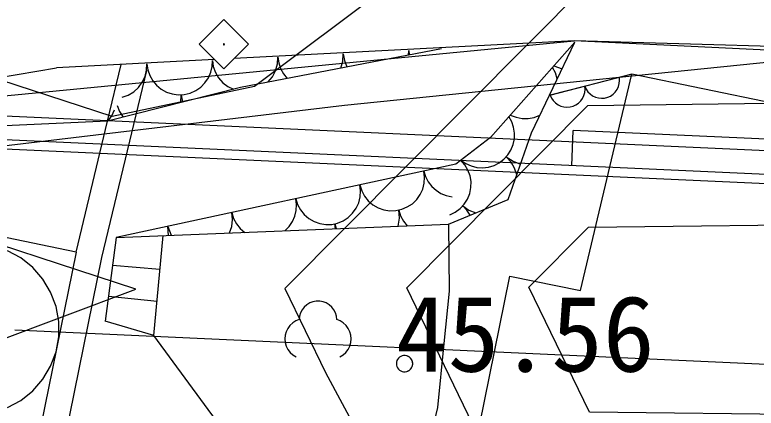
# Model space of a CAD drawing. Extents: x 42655 to 43811, y -141820 to -141156.
# Drawn here: x 43648.75 to 43660.06, y -141351.2 to -141345.21 of the extents above; entities that cross this region are included whole.
import ezdxf

# ---------------------------------------------------------------- set-up
doc = ezdxf.new("R2010")
doc.units = 0
for name, color, linetype in [('D-BMK-HTXT_1', 7, 'Continuous'), ('ZE_HICN', 7, 'Continuous'), ('ZE_LWCN', 7, 'Continuous'), ('地形', 7, 'Continuous'), ('現況道路ﾊｯﾁ', 7, 'Continuous')]:
    doc.layers.add(name, color=color, linetype=linetype)

msp = doc.modelspace()

# ---------------------------------------------------------------- linework, layer by layer
at = {"layer": 'D-BMK-HTXT_1'}
msp.add_lwpolyline([(43648.635, -141351.192), (43648.84, -141351.082), (43649.023, -141350.936), (43649.176, -141350.761), (43649.295, -141350.561), (43649.377, -141350.343), (43649.419, -141350.113), (43649.419, -141349.88), (43649.377, -141349.651), (43649.295, -141349.433), (43649.176, -141349.233), (43649.023, -141349.057), (43648.84, -141348.912), (43648.635, -141348.801)], dxfattribs=at)
at = {"layer": 'ZE_HICN'}
msp.add_lwpolyline([(43670.166, -141358.665), (43667.725, -141358.014), (43663.61, -141355.487), (43662.608, -141351.884), (43660.983, -141351.301), (43657.517, -141351.264), (43656.594, -141349.358), (43657.503, -141348.444), (43661.814, -141348.392), (43662.588, -141347.666), (43663.879, -141347.759), (43667.681, -141348.645), (43668.638, -141349.3)], dxfattribs=at)
at = {"layer": 'ZE_LWCN'}
for points in [[(43670.156, -141340.015), (43667.636, -141339.291), (43665.818, -141339.189), (43662.55, -141339.651), (43660.092, -141340.198), (43657.476, -141342.639), (43656.548, -141343.195), (43652.405, -141346.296), (43650.235, -141346.757), (43647.315, -141345.805)], [(43672.041, -141343.121), (43667.648, -141341.858), (43663.811, -141341.644), (43662.56, -141341.821), (43661.619, -141342.03), (43660.391, -141343.177), (43658.75, -141344.716), (43657.486, -141344.731), (43652.867, -141349.375), (43653.488, -141350.658), (43656.108, -141355.523), (43657.543, -141356.746), (43661.312, -141357.098), (43662.633, -141357.221), (43664.475, -141357.711), (43667.733, -141359.712), (43669.028, -141360.057)], [(43669.597, -141359.361), (43667.729, -141358.863), (43663.03, -141355.977), (43662.627, -141355.87), (43662.338, -141355.843), (43658.775, -141355.51), (43657.822, -141355.168), (43657.535, -141355.165), (43654.731, -141349.366), (43657.495, -141346.587), (43660.282, -141346.554), (43662.572, -141344.405), (43666.396, -141344.681), (43667.663, -141344.976), (43671.208, -141347.405)], [(43647.337, -141350.606), (43650.597, -141349.386), (43647.327, -141348.32), (43642.867, -141349.423), (43647.337, -141350.606)]]:
    msp.add_lwpolyline(points, dxfattribs=at)
at = {"layer": '地形'}
for p, q in [((43646.378, -141346.651), (43657.284, -141345.602)), ((43668.134, -141346.119), (43657.284, -141345.602)), ((43665.232, -141347.509), (43626.082, -141345.728)), ((43651.797, -141345.888), (43649.384, -141346.013)), ((43650.163, -141346.825), (43650.371, -141345.962)), ((43665.216, -141347.869), (43626.066, -141346.088)), ((43644.324, -141346.875), (43649.384, -141346.013)), ((43658.167, -141346.11), (43656.908, -141346.434)), ((43657.383, -141349.41), (43658.167, -141346.11)), ((43667.506, -141348.037), (43658.167, -141346.11)), ((43666.822, -141348.082), (43626.06, -141346.228)), ((43657.974, -141346.159), (43656.92, -141346.431)), ((43650.163, -141346.825), (43644.868, -141347.075)), ((43649.682, -141348.821), (43650.163, -141346.825)), ((43657.247, -141347.506), (43657.271, -141346.967)), ((43665.24, -141347.329), (43657.271, -141346.967)), ((43649.682, -141348.821), (43644.802, -141347.813)), ((43650.297, -141348.599), (43650.125, -141349.873)), ((43650.871, -141350.091), (43651.01, -141348.571)), ((43649.682, -141348.821), (43649.126, -141351.553)), ((43650.963, -141349.089), (43650.24, -141349.024)), ((43655.415, -141353.55), (43656.305, -141349.19)), ((43656.305, -141349.19), (43657.383, -141349.41)), ((43650.918, -141349.577), (43650.176, -141349.499)), ((43650.871, -141350.091), (43650.125, -141349.873)), ((43667.605, -141350.87), (43648.749, -141350.013)), ((43651.943, -141351.553), (43650.871, -141350.091))]:
    msp.add_line(p, q, dxfattribs=at)
for points in [[(43549.208, -141319.961), (43556.867, -141320.753), (43567.431, -141322.178), (43571.973, -141322.864), (43574.086, -141324.131), (43583.297, -141331.692), (43590.642, -141338.347), (43593.759, -141341.303), (43600.265, -141345.426), (43603.065, -141346.799), (43608.248, -141348.229), (43613.847, -141348.387), (43631.813, -141349.201), (43653.781, -141346.583), (43661.115, -141345.834), (43670.949, -141346.829), (43671.768, -141347.675)], [(43651.938, -141345.279), (43651.563, -141345.654), (43651.938, -141346.029), (43652.313, -141345.654), (43651.938, -141345.279)], [(43657.295, -141345.623), (43656.007, -141347.076), (43655.48, -141347.482), (43650.297, -141348.599), (43655.368, -141348.397), (43656.277, -141348.02), (43656.634, -141347.002), (43657.295, -141345.623)], [(43651.931, -141345.654), (43651.931, -141345.656), (43651.931, -141345.657), (43651.932, -141345.658), (43651.933, -141345.659), (43651.934, -141345.66), (43651.935, -141345.661), (43651.936, -141345.662), (43651.937, -141345.662), (43651.939, -141345.662), (43651.94, -141345.662), (43651.941, -141345.661), (43651.942, -141345.661), (43651.943, -141345.66), (43651.944, -141345.659), (43651.945, -141345.658), (43651.946, -141345.656), (43651.946, -141345.655), (43651.946, -141345.654), (43651.946, -141345.652), (43651.945, -141345.651), (43651.944, -141345.65), (43651.943, -141345.649), (43651.942, -141345.648), (43651.941, -141345.648), (43651.94, -141345.647), (43651.939, -141345.647), (43651.937, -141345.647), (43651.936, -141345.647), (43651.935, -141345.648), (43651.934, -141345.649), (43651.933, -141345.65), (43651.932, -141345.651), (43651.931, -141345.652), (43651.931, -141345.653), (43651.931, -141345.654)], [(43669.415, -141346.345), (43668.835, -141346.137), (43667.715, -141346.021), (43662.256, -141345.743), (43657.284, -141345.602), (43652.096, -141345.872)], [(43655.258, -141345.722), (43652.192, -141346.314), (43650.163, -141346.825)], [(43654.758, -141345.818), (43654.759, -141345.747)], [(43654.759, -141345.747), (43654.768, -141345.816)], [(43652.611, -141346.233), (43652.679, -141346.151), (43652.728, -141346.057), (43652.756, -141345.955), (43652.762, -141345.849)], [(43652.762, -141345.849), (43652.775, -141345.939), (43652.804, -141346.026), (43652.848, -141346.106), (43652.906, -141346.176)], [(43653.721, -141346.019), (43653.753, -141345.91), (43653.76, -141345.798)], [(43653.76, -141345.798), (43653.777, -141345.902), (43653.815, -141346)], [(43650.385, -141346.461), (43650.478, -141346.428), (43650.562, -141346.378), (43650.635, -141346.312), (43650.694, -141346.233), (43650.736, -141346.144), (43650.76, -141346.049), (43650.764, -141345.951)], [(43650.764, -141345.951), (43650.777, -141346.042), (43650.807, -141346.129), (43650.852, -141346.21), (43650.912, -141346.28), (43650.983, -141346.339), (43651.064, -141346.384), (43651.151, -141346.412), (43651.243, -141346.425), (43651.335, -141346.42), (43651.425, -141346.398), (43651.509, -141346.361), (43651.585, -141346.308), (43651.65, -141346.243), (43651.702, -141346.166), (43651.738, -141346.082), (43651.759, -141345.992), (43651.763, -141345.9)], [(43651.763, -141345.9), (43651.777, -141345.995), (43651.809, -141346.085), (43651.858, -141346.168), (43651.921, -141346.24), (43651.998, -141346.298), (43652.083, -141346.341)], [(43657.027, -141346.182), (43656.998, -141346.092), (43656.953, -141346.008)], [(43656.973, -141345.985), (43657.1, -141346.03)], [(43650.759, -141346.056), (43650.072, -141348.907), (43649.517, -141351.635), (43648.918, -141354.385), (43648.582, -141356.238)], [(43657.447, -141346.295), (43657.466, -141346.339), (43657.493, -141346.378), (43657.527, -141346.412), (43657.565, -141346.44), (43657.608, -141346.461), (43657.654, -141346.473), (43657.702, -141346.478), (43657.749, -141346.474), (43657.796, -141346.462), (43657.839, -141346.443), (43657.878, -141346.416), (43657.912, -141346.382), (43657.94, -141346.343), (43657.961, -141346.3), (43657.973, -141346.254), (43657.978, -141346.207), (43657.974, -141346.159)], [(43656.92, -141346.431), (43656.939, -141346.474), (43656.966, -141346.514), (43657, -141346.548), (43657.038, -141346.576), (43657.081, -141346.596), (43657.127, -141346.609), (43657.175, -141346.614), (43657.222, -141346.61), (43657.268, -141346.598), (43657.312, -141346.578), (43657.351, -141346.551), (43657.385, -141346.518), (43657.413, -141346.479), (43657.433, -141346.436), (43657.446, -141346.39), (43657.451, -141346.343), (43657.447, -141346.295)], [(43651.281, -141346.543), (43651.289, -141346.425)], [(43651.289, -141346.425), (43651.308, -141346.536)], [(43650.174, -141346.822), (43650.229, -141346.743), (43650.267, -141346.655)], [(43650.309, -141346.586), (43650.346, -141346.68), (43650.401, -141346.765)], [(43655.557, -141347.423), (43655.631, -141347.473), (43655.712, -141347.509), (43655.799, -141347.531), (43655.887, -141347.537), (43655.976, -141347.527), (43656.061, -141347.501), (43656.141, -141347.461), (43656.212, -141347.407), (43656.272, -141347.341), (43656.32, -141347.266), (43656.353, -141347.183), (43656.372, -141347.096), (43656.374, -141347.007), (43656.361, -141346.919), (43656.332, -141346.835), (43656.289, -141346.757)], [(43656.31, -141346.733), (43656.397, -141346.768), (43656.489, -141346.786), (43656.582, -141346.787), (43656.674, -141346.77), (43656.762, -141346.736)], [(43656.249, -141347.369), (43656.351, -141347.438), (43656.466, -141347.481)], [(43656.408, -141347.646), (43656.376, -141347.543), (43656.322, -141347.449), (43656.249, -141347.369)], [(43655.386, -141348.254), (43655.469, -141348.214), (43655.543, -141348.16), (43655.606, -141348.093), (43655.655, -141348.015), (43655.69, -141347.93), (43655.709, -141347.84), (43655.71, -141347.748), (43655.695, -141347.658), (43655.664, -141347.571), (43655.617, -141347.492), (43655.557, -141347.423)], [(43654.014, -141347.798), (43654.042, -141347.886), (43654.085, -141347.968), (43654.143, -141348.04), (43654.212, -141348.1), (43654.292, -141348.146), (43654.379, -141348.177), (43654.47, -141348.192), (43654.562, -141348.189), (43654.653, -141348.17), (43654.738, -141348.134), (43654.815, -141348.084), (43654.881, -141348.02), (43654.935, -141347.944), (43654.974, -141347.861), (43654.996, -141347.771), (43655.002, -141347.679), (43654.991, -141347.588)], [(43654.991, -141347.588), (43655.018, -141347.672), (43655.058, -141347.75), (43655.112, -141347.82), (43655.177, -141347.88), (43655.252, -141347.927), (43655.333, -141347.96), (43655.42, -141347.979)], [(43653.036, -141348.009), (43653.064, -141348.097), (43653.107, -141348.178), (43653.165, -141348.251), (43653.235, -141348.311), (43653.315, -141348.357), (43653.402, -141348.388), (43653.493, -141348.403), (43653.585, -141348.4), (43653.675, -141348.381), (43653.76, -141348.345), (43653.837, -141348.294), (43653.904, -141348.23), (43653.957, -141348.155), (43653.996, -141348.071), (43654.019, -141347.982), (43654.025, -141347.89), (43654.014, -141347.798)], [(43652.87, -141348.497), (43652.933, -141348.433), (43652.984, -141348.358), (43653.021, -141348.276), (43653.042, -141348.188), (43653.047, -141348.098), (43653.036, -141348.009)], [(43655.586, -141348.117), (43655.679, -141348.182), (43655.784, -141348.225)], [(43655.698, -141348.26), (43655.648, -141348.183), (43655.586, -141348.117)], [(43652.026, -141348.53), (43652.059, -141348.43), (43652.07, -141348.325), (43652.059, -141348.22)], [(43652.059, -141348.22), (43652.086, -141348.308), (43652.13, -141348.389), (43652.187, -141348.461), (43652.257, -141348.521)], [(43654.599, -141348.428), (43654.619, -141348.305), (43654.608, -141348.182)], [(43654.608, -141348.182), (43654.635, -141348.269), (43654.678, -141348.35), (43654.736, -141348.422)], [(43651.081, -141348.43), (43651.132, -141348.566)], [(43651.091, -141348.568), (43651.081, -141348.43)], [(43655.368, -141348.397), (43655.379, -141349.42), (43655.295, -141350.216), (43655.197, -141351.193), (43655.1, -141351.598), (43654.854, -141352.121), (43654.304, -141352.185), (43653.41, -141352.031), (43652.544, -141351.822), (43651.943, -141351.553)], [(43653.63, -141348.392), (43653.652, -141348.465)], [(43653.641, -141348.466), (43653.63, -141348.392)], [(43653.661, -141349.851), (43653.655, -141349.799), (43653.641, -141349.748), (43653.617, -141349.701), (43653.585, -141349.66), (43653.546, -141349.625), (43653.502, -141349.597), (43653.453, -141349.578), (43653.401, -141349.569), (43653.349, -141349.569), (43653.297, -141349.578), (43653.248, -141349.597), (43653.204, -141349.625), (43653.165, -141349.66), (43653.133, -141349.701), (43653.109, -141349.748), (43653.094, -141349.799), (43653.089, -141349.851)], [(43653.089, -141349.851), (43653.037, -141349.871), (43652.989, -141349.901), (43652.947, -141349.939), (43652.913, -141349.985), (43652.888, -141350.035), (43652.873, -141350.09), (43652.869, -141350.146), (43652.874, -141350.202), (43652.89, -141350.256), (43652.916, -141350.306), (43652.951, -141350.351), (43652.993, -141350.389), (43653.042, -141350.417)], [(43653.708, -141350.417), (43653.757, -141350.389), (43653.799, -141350.351), (43653.834, -141350.306), (43653.859, -141350.256), (43653.876, -141350.202), (43653.881, -141350.146), (43653.877, -141350.09), (43653.862, -141350.035), (43653.837, -141349.985), (43653.803, -141349.939), (43653.761, -141349.901), (43653.713, -141349.871), (43653.661, -141349.851)], [(43654.821, -141350.523), (43654.819, -141350.5), (43654.812, -141350.477), (43654.802, -141350.457), (43654.788, -141350.438), (43654.771, -141350.423), (43654.752, -141350.411), (43654.73, -141350.402), (43654.707, -141350.398), (43654.684, -141350.398), (43654.662, -141350.402), (43654.64, -141350.411), (43654.62, -141350.423), (43654.603, -141350.438), (43654.59, -141350.457), (43654.579, -141350.477), (43654.573, -141350.5), (43654.571, -141350.523)], [(43654.571, -141350.523), (43654.573, -141350.545), (43654.579, -141350.566), (43654.589, -141350.587), (43654.602, -141350.605), (43654.618, -141350.62), (43654.637, -141350.633), (43654.657, -141350.641), (43654.679, -141350.646), (43654.701, -141350.647), (43654.724, -141350.644), (43654.745, -141350.637), (43654.765, -141350.627), (43654.782, -141350.613), (43654.797, -141350.596), (43654.808, -141350.577), (43654.816, -141350.556), (43654.82, -141350.534), (43654.82, -141350.511), (43654.816, -141350.489), (43654.808, -141350.468), (43654.797, -141350.449), (43654.782, -141350.432), (43654.765, -141350.418), (43654.745, -141350.408), (43654.724, -141350.401), (43654.701, -141350.398), (43654.679, -141350.399), (43654.657, -141350.404), (43654.637, -141350.412), (43654.618, -141350.425), (43654.602, -141350.44), (43654.589, -141350.458), (43654.579, -141350.479), (43654.573, -141350.5), (43654.571, -141350.523)], [(43654.571, -141350.523), (43654.573, -141350.545), (43654.579, -141350.568), (43654.59, -141350.588), (43654.603, -141350.607), (43654.62, -141350.622), (43654.64, -141350.634), (43654.662, -141350.643), (43654.684, -141350.647), (43654.707, -141350.647), (43654.73, -141350.643), (43654.752, -141350.634), (43654.771, -141350.622), (43654.788, -141350.607), (43654.802, -141350.588), (43654.812, -141350.568), (43654.819, -141350.545), (43654.821, -141350.523)]]:
    msp.add_lwpolyline(points, dxfattribs=at)
at = {"layer": '現況道路ﾊｯﾁ'}
msp.add_lwpolyline([(43613.847, -141348.387), (43631.813, -141349.201), (43653.781, -141346.583), (43661.115, -141345.834), (43670.949, -141346.829), (43671.768, -141347.675), (43672.39, -141343.247), (43666.601, -141343.483), (43659.63, -141342.657), (43653.133, -141342.421), (43647.107, -141343.483), (43638.545, -141344.705), (43633.945, -141345.29), (43631.017, -141345.625), (43626.083, -141345.458), (43621.483, -141345.458), (43611.781, -141345.207)], dxfattribs=at)

# ---------------------------------------------------------------- texts
at = {"layer": '地形'}
msp.add_text('45.56', height=1.1606, dxfattribs=at).set_placement((43654.564, -141350.645))

doc.saveas('drawing.dxf')
